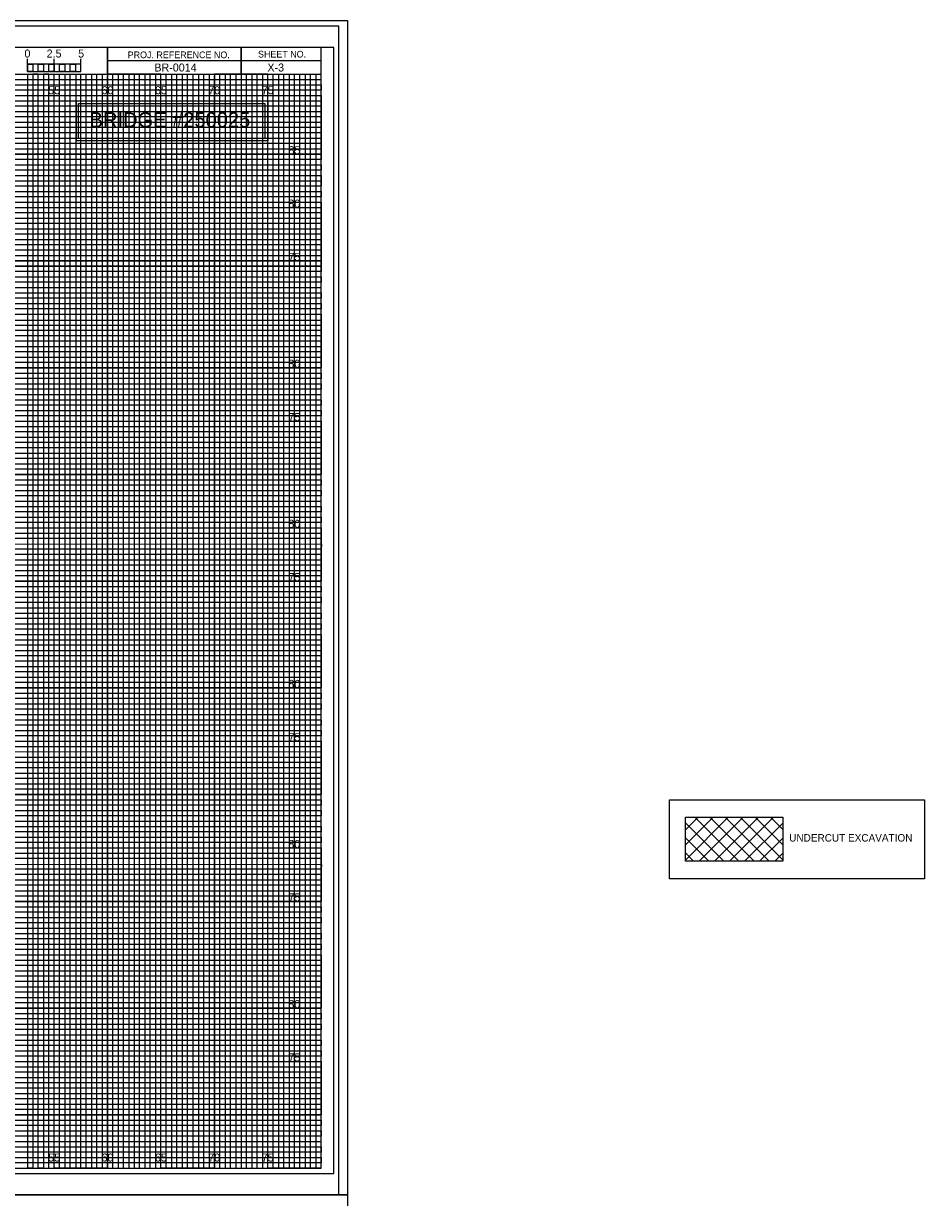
# Model space of a CAD drawing. Extents: x -8 to 533, y -20 to 768.
# Drawn here: x 132.1 to 216.5, y 217.2 to 327.2 of the extents above; entities that cross this region are included whole.
import ezdxf

# ---------------------------------------------------------------- set-up
doc = ezdxf.new("R2010")
doc.units = 0
for name, color, linetype in [('Old_Level_1', 7, 'Continuous'), ('Old_Level_34', 7, 'Continuous'), ('Prop Grid Mask', 7, 'Continuous'), ('Prop XS Bar Scale Labels', 7, 'Continuous'), ('Prop XS Elevation Labels', 7, 'Continuous'), ('Prop XS Offset Labels', 7, 'Continuous'), ('Prop XS Project Number', 7, 'Continuous'), ('Prop XS Sheet Number', 7, 'Continuous'), ('Prop XS Side Slope Text', 7, 'Continuous'), ('Prop XS Undercut Exc', 7, 'Continuous'), ('Sheet Cross Section CELL', 7, 'Continuous'), ('Sheet Cross Section Grid Major CELL', 7, 'Continuous'), ('Sheet Cross Section Grid Middle CELL', 7, 'Continuous'), ('Sheet Cross Section Grid Minor 1 CELL', 7, 'Continuous'), ('Sheet Cross Section Grid Minor 2 CELL', 7, 'Continuous'), ('Sheet Cross Section Scale CELL', 7, 'Continuous'), ('Sheet Cutting Line CELL', 7, 'Continuous'), ('Sheet DOT Grid CELL', 7, 'Continuous'), ('Sheet Plot Border Inside CELL', 7, 'Continuous'), ('Sheet Plot Border Outside CELL', 7, 'Continuous'), ('WEI Plot Border', 7, 'Continuous')]:
    doc.layers.add(name, color=color, linetype=linetype)

msp = doc.modelspace()

# ---------------------------------------------------------------- linework, layer by layer
at = {"layer": 'Old_Level_34'}
msp.add_lwpolyline([(137.26, 319.75), (154.74, 319.75), (154.74, 316.46), (137.26, 316.46)], close=True, dxfattribs=at)
at = {"layer": 'Prop Grid Mask'}
for points in [[(137.08, 320), (155, 320), (155, 316.24), (137.08, 316.24)], [(192.64, 254.5), (216.53, 254.5), (216.53, 247.11), (192.64, 247.11)]]:
    msp.add_lwpolyline(points, close=True, dxfattribs=at)
at = {"layer": 'Prop XS Undercut Exc'}
for p, q in [((194.13, 248.87), (198.14, 252.88)), ((194.13, 250.29), (196.73, 252.88)), ((194.13, 251.7), (195.31, 252.88)), ((194.13, 252.36), (197.73, 248.76)), ((195.01, 252.88), (199.14, 248.76)), ((195.43, 248.76), (199.55, 252.88)), ((196.43, 252.88), (200.56, 248.76)), ((196.84, 248.76), (200.97, 252.88)), ((197.84, 252.88), (201.97, 248.76)), ((198.25, 248.76), (202.38, 252.88)), ((199.26, 252.88), (203.25, 248.89)), ((199.67, 248.76), (203.25, 252.34)), ((200.67, 252.88), (203.25, 250.31)), ((202.09, 252.88), (203.25, 251.72)), ((194.13, 250.94), (196.31, 248.76)), ((201.08, 248.76), (203.25, 250.92)), ((194.13, 249.53), (194.9, 248.76)), ((202.5, 248.76), (203.25, 249.51))]:
    msp.add_line(p, q, dxfattribs=at)
msp.add_lwpolyline([(194.13, 252.88), (203.25, 252.88), (203.25, 248.76), (194.13, 248.76)], close=True, dxfattribs=at)
at = {"layer": 'Sheet Cross Section CELL'}
for p, q in [((152.5, 325), (152.5, 322.5)), ((152.5, 322.5), (152.5, 325)), ((160, 323.75), (140, 323.75)), ((140, 323.75), (140, 322.5)), ((140, 322.5), (160, 322.5))]:
    msp.add_line(p, q, dxfattribs=at)
for points in [[(160, 325), (0, 325), (0, 220), (160, 220)], [(140, 325), (130, 325), (130, 322.51), (140, 322.51)], [(160, 325), (140, 325), (140, 322.5), (160, 322.5)]]:
    msp.add_lwpolyline(points, close=True, dxfattribs=at)
at = {"layer": 'Sheet Cross Section Grid Major CELL'}
for p, q in [((135, 220), (135, 322.5)), ((145, 322.5), (140, 322.5)), ((140, 322.5), (140, 220)), ((145, 220), (145, 322.5)), ((155, 322.5), (150, 322.5)), ((150, 322.5), (150, 220)), ((155, 220), (155, 322.5)), ((140, 220), (135, 220)), ((150, 220), (145, 220)), ((160, 220), (155, 220)), ((160, 220), (160, 220))]:
    msp.add_line(p, q, dxfattribs=at)
for points in [[(0, 320), (160, 320), (160, 315), (0, 315)], [(0, 310), (160, 310), (160, 305), (0, 305)], [(0, 300), (160, 300), (160, 295), (0, 295)], [(0, 290), (160, 290), (160, 285), (0, 285)], [(0, 280), (160, 280), (160, 275), (0, 275)], [(0, 270), (160, 270), (160, 265), (0, 265)], [(0, 260), (160, 260), (160, 255), (0, 255)], [(0, 250), (160, 250), (160, 245), (0, 245)], [(0, 240), (160, 240), (160, 235), (0, 235)], [(0, 230), (160, 230), (160, 225), (0, 225)]]:
    msp.add_lwpolyline(points, dxfattribs=at)
at = {"layer": 'Sheet Cross Section Grid Middle CELL'}
for points in [[(0, 322.5), (137.5, 322.5)], [(130, 322.5), (132.5, 322.5), (132.5, 220), (137.5, 220), (137.5, 322.5), (142.5, 322.5), (142.5, 220), (147.5, 220), (147.5, 322.5), (152.5, 322.5), (152.5, 220), (157.5, 220), (157.5, 322.5)], [(0, 312.5), (160, 312.5), (160, 317.5), (0, 317.5)], [(0, 302.5), (160, 302.5), (160, 307.5), (0, 307.5)], [(0, 292.5), (160, 292.5), (160, 297.5), (0, 297.5)], [(0, 282.5), (160, 282.5), (160, 287.5), (0, 287.5)], [(0, 272.5), (160, 272.5), (160, 277.5), (0, 277.5)], [(0, 262.5), (160, 262.5), (160, 267.5), (0, 267.5)], [(0, 252.5), (160, 252.5), (160, 257.5), (0, 257.5)], [(0, 242.5), (160, 242.5), (160, 247.5), (0, 247.5)], [(0, 232.5), (160, 232.5), (160, 237.5), (0, 237.5)], [(0, 222.5), (160, 222.5), (160, 227.5), (0, 227.5)]]:
    msp.add_lwpolyline(points, dxfattribs=at)
at = {"layer": 'Sheet Cross Section Grid Minor 1 CELL'}
msp.add_line((0, 322), (160, 322), dxfattribs=at)
for points in [[(0, 321.5), (135, 321.5), (160, 321.5), (160, 321), (0, 321)], [(0, 320.5), (160, 320.5), (160, 319.5), (0, 319.5)], [(0, 319), (160, 319), (160, 318.5), (0, 318.49)], [(0, 318), (160, 318), (160, 317), (0, 317)], [(0, 316.5), (160, 316.5), (160, 316), (0, 316)], [(0, 315.5), (160, 315.5), (160, 314.5), (0, 314.5)], [(0, 314), (160, 314), (160, 313.5), (0, 313.5)], [(0, 313), (160, 313), (160, 312), (0, 312)], [(0, 311.5), (160, 311.5), (160, 311), (0, 311)], [(0, 310.5), (160, 310.5), (160, 309.5), (0, 309.5)], [(0, 309), (160, 309), (160, 308.5), (0, 308.5)], [(0, 308), (160, 308), (160, 306.98), (160, 306.5), (160, 306), (0, 306)], [(0, 307), (160, 307), (160, 306.5), (0, 306.5)], [(0, 305.5), (160, 305.5), (160, 304.5), (0, 304.51)], [(0, 304.51), (160, 304.5), (160, 304), (0, 304)], [(0, 303.5), (160, 303.5), (160, 303), (0, 303)], [(0, 302), (160, 302), (160, 301.5), (0, 301.5)], [(0, 301), (160, 301), (160, 300.5), (0, 300.5)], [(-0.04, 299.44), (160, 299.44), (160, 298.94), (-0.04, 298.94)], [(0, 298.5), (160, 298.5), (160, 298), (0, 298)], [(0, 297), (160, 297), (160, 296.5), (0, 296.5)], [(0, 296), (160, 296), (160, 295.5), (0, 295.5)], [(0, 294.5), (160, 294.5), (160, 294), (0, 294)], [(0, 293.5), (160, 293.5), (160, 293), (0, 293)], [(0, 292), (160, 292), (160, 291.5), (0, 291.5)], [(0, 291), (160, 291), (160, 290.5), (0, 290.5)], [(0, 289.5), (160, 289.5), (160, 288.99), (0, 289)], [(0, 288.5), (160, 288.5), (160, 288), (0, 288)], [(0, 287), (160, 287), (160, 286.5), (0, 286.5)], [(0, 286), (160, 286), (160, 285.5), (0, 285.5)], [(0, 284.5), (160, 284.5), (160, 284), (0, 284)], [(0, 283.5), (160, 283.5), (160, 283), (0, 283)], [(0, 282), (160, 282), (160, 281.5), (0, 281.5)], [(0, 281), (160, 281), (160, 280.5), (0, 280.5)], [(0, 279.5), (160, 279.5), (160, 279), (0, 279)], [(0, 278.5), (160.03, 278.45), (160, 278), (0, 278)], [(0, 277), (160, 277), (160, 276.5), (0, 276.5)], [(0, 276), (160, 276), (160, 275.5), (0, 275.5)], [(0, 274.5), (160, 274.5), (160, 274), (0, 274)], [(0, 273.5), (160, 273.5), (160, 273), (0, 273)], [(0, 272), (160, 272), (160, 271.5), (0, 271.5)], [(0, 271), (160, 271), (160, 270.5), (0, 270.5)], [(0, 269.5), (160, 269.5), (160, 269), (0, 269)], [(0, 268.5), (160, 268.5), (160, 268), (0, 268)], [(0, 267), (160, 267), (160, 266.5), (0, 266.5)], [(0, 266), (160, 266), (160, 265.5), (0, 265.5)], [(0, 264.5), (160, 264.5), (160, 264), (0, 264)], [(0, 263.5), (160, 263.5), (160, 263), (0, 263)], [(0, 262), (160, 262), (160, 261.5), (0, 261.5)], [(0, 261), (160, 261), (160, 260.5), (0, 260.5)], [(0, 259.5), (160, 259.5), (160, 258.99), (0, 259)], [(0, 258.5), (160, 258.5), (160, 258), (0, 258)], [(0, 257), (160, 257), (160, 256.5), (0, 256.5)], [(0, 256), (160, 256), (160, 255.5), (0, 255.5)], [(0, 254.5), (160, 254.5), (160, 254), (0, 254)], [(0, 253.5), (160, 253.5), (160, 253), (0, 253)], [(0, 252), (160, 252), (160, 251.5), (0, 251.5)], [(0, 251), (160, 251), (160, 250.5), (0, 250.5)], [(0, 249.5), (160, 249.5), (160, 249), (0, 249)], [(0, 248.5), (160.03, 248.46), (160, 248), (0, 248)], [(0, 247), (160, 247), (160, 246.5), (0, 246.5)], [(0, 246), (160, 246), (160, 245.5), (0, 245.5)], [(0, 244.5), (160, 244.5), (160, 244), (0, 244)], [(0, 243.5), (160, 243.5), (160, 243), (0, 243)], [(0, 242), (160, 242), (160, 241.5), (0, 241.5)], [(0, 241), (160, 241), (160, 240.5), (0, 240.5)], [(0, 239.5), (160, 239.5), (160, 239), (0, 239)], [(0, 238.5), (160, 238.5), (160, 238), (0, 238)], [(0, 237), (160, 237), (160, 236.5), (0, 236.5)], [(0, 236), (160, 236), (160, 235.5), (0, 235.5)], [(0, 234.5), (160, 234.5), (160, 234), (0, 234)], [(0, 233.5), (160, 233.5), (160, 233), (0, 233)], [(0, 232), (160, 232), (160, 231.5), (0, 231.5)], [(0, 231), (160, 231), (160, 230.5), (0, 230.5)], [(0, 229.5), (160, 229.5), (160, 229), (0, 229)], [(0, 228.5), (160, 228.5), (160, 228), (0, 228)], [(0, 227), (160, 227), (160, 226.5), (0, 226.5)], [(0, 226), (160, 226), (160, 225.5), (0, 225.5)], [(0, 224.5), (160, 224.5), (160, 224), (0, 224)], [(0, 223.5), (160, 223.5), (160, 223), (0, 223)], [(0, 222), (160, 222), (160, 221.5), (0, 221.5)], [(0, 221), (160, 221), (160, 220.5), (0, 220.5)]]:
    msp.add_lwpolyline(points, dxfattribs=at)
at = {"layer": 'Sheet Cross Section Grid Minor 2 CELL'}
for p, q in [((133.5, 322.5), (133, 322.5)), ((133, 322.5), (133, 220)), ((133.5, 220), (133.5, 322.5)), ((134.5, 322.5), (134, 322.5)), ((134, 322.5), (134, 220)), ((134.5, 220), (134.5, 322.5)), ((133, 220), (132.5, 220)), ((134, 220), (133.5, 220))]:
    msp.add_line(p, q, dxfattribs=at)
for points in [[(135, 220), (135.49, 220), (135.49, 322.5), (136, 322.5), (136, 220)], [(136, 220), (136.5, 220), (136.5, 322.5), (137.03, 322.5), (137.03, 220)], [(137.5, 220), (138, 220), (138, 322.5), (138.5, 322.5), (138.5, 220)], [(138.5, 220), (139, 220), (139, 322.5), (139.5, 322.5), (139.5, 220)], [(140, 220), (140.5, 220), (140.5, 322.5), (141, 322.5), (141, 220)], [(141, 220), (141.5, 220), (141.5, 322.5), (142, 322.5), (142, 220)], [(142.5, 220), (143, 220), (143, 322.5), (143.5, 322.5), (143.5, 220)], [(143.5, 220), (144, 220), (144, 322.5), (144.5, 322.5), (144.5, 220)], [(145, 220), (145.5, 220), (145.5, 322.5), (146, 322.5), (146, 220)], [(146, 220), (146.5, 220), (146.5, 322.5), (147, 322.5), (147, 220)], [(147.5, 220), (148, 220), (148, 322.5), (148.5, 322.5), (148.5, 220)], [(148.5, 220), (149, 220), (149, 322.5), (149.5, 322.5), (149.5, 220)], [(150, 220), (150.5, 220), (150.5, 322.5), (151, 322.5), (151, 220)], [(151, 220), (151.5, 220), (151.5, 322.5), (152, 322.5), (152, 220)], [(152.5, 220), (153, 220), (153, 322.5), (153.5, 322.5), (153.5, 220)], [(153.5, 220), (154, 220), (154, 322.5), (154.5, 322.5), (154.5, 220)], [(155, 220), (155.5, 220), (155.5, 322.5), (156, 322.5), (156, 220)], [(156, 220), (156.5, 220), (156.5, 322.5), (157, 322.5), (157, 220)], [(157.5, 220), (158, 220), (158, 322.5), (158.5, 322.5), (158.5, 220)], [(158.5, 220), (159, 220), (159, 322.5), (159.5, 322.5), (159.5, 220)]]:
    msp.add_lwpolyline(points, dxfattribs=at)
at = {"layer": 'Sheet Cross Section Scale CELL'}
for p, q in [((132.5, 322.75), (132.5, 323.95)), ((132.5, 323.45), (132.5, 323.95)), ((135, 322.75), (135, 323.95)), ((137.5, 322.75), (137.5, 323.95)), ((137.5, 323.45), (137.5, 323.95))]:
    msp.add_line(p, q, dxfattribs=at)
for points in [[(137.5, 323.45), (132.5, 323.45), (132.5, 322.75), (137.5, 322.75)], [(132.5, 323.45), (133, 323.45), (133, 322.75), (132.5, 322.75)], [(133.5, 323.45), (134, 323.45), (134, 322.75), (133.5, 322.75)], [(134.5, 323.45), (135, 323.45), (135, 322.75), (134.5, 322.75)], [(135.5, 323.45), (136, 323.45), (136, 322.75), (135.5, 322.75)], [(136.5, 323.45), (137, 323.45), (137, 322.75), (136.5, 322.75)]]:
    msp.add_lwpolyline(points, close=True, dxfattribs=at)
at = {"layer": 'Sheet Cutting Line CELL'}
for p, q in [((161.65, 327), (-6.7, 327)), ((-6.7, 217.5), (161.65, 217.5))]:
    msp.add_line(p, q, dxfattribs=at)
at = {"layer": 'Sheet DOT Grid CELL'}
for p, q in [((135, 220), (135, 322.34)), ((140, 220), (140, 322.34)), ((145, 220), (145, 322.34)), ((150, 220), (150, 322.34)), ((155, 220), (155, 322.34)), ((0, 320), (160, 320)), ((0, 315), (160, 315)), ((0, 310), (160, 310)), ((0, 305), (160, 305)), ((0, 300), (160, 300)), ((0, 295), (160, 295)), ((0, 290), (160, 290)), ((0, 285), (160, 285)), ((0, 280), (160, 280)), ((0, 275), (160, 275)), ((0, 270), (160, 270)), ((0, 265), (160, 265)), ((0, 260), (160, 260)), ((0, 255), (160, 255)), ((0, 250), (160, 250)), ((0, 245), (160, 245)), ((0, 240), (160, 240)), ((0, 235), (160, 235)), ((0, 230), (160, 230)), ((0, 225), (160, 225))]:
    msp.add_line(p, q, dxfattribs=at)
at = {"layer": 'Sheet Plot Border Inside CELL'}
msp.add_lwpolyline([(-5.4, 219.5), (161.2, 219.5), (161.2, 325), (-5.4, 325)], close=True, dxfattribs=at)
at = {"layer": 'Sheet Plot Border Outside CELL'}
msp.add_lwpolyline([(-6.7, 217.5), (161.65, 217.5), (161.65, 327), (-6.7, 327)], close=True, dxfattribs=at)
at = {"layer": 'WEI Plot Border'}
for points in [[(-7.5, 217.5), (162.5, 217.5), (162.5, 327.5), (-7.5, 327.5)], [(-7.5, 107.5), (162.5, 107.5), (162.5, 217.5), (-7.5, 217.5)]]:
    msp.add_lwpolyline(points, close=True, dxfattribs=at)

# ---------------------------------------------------------------- texts
at = {"layer": 'Old_Level_1'}
msp.add_text('BRIDGE #250025', height=1.4062, rotation=360, dxfattribs=at).set_placement((138.31, 317.52))
at = {"layer": 'Prop XS Bar Scale Labels'}
for s, p in [('2.5', (134.29, 324.06)), ('5', (137.24, 324.06))]:
    msp.add_text(s, height=0.75, dxfattribs=at).set_placement(p)
at = {"layer": 'Prop XS Elevation Labels'}
for s, p in [('85', (156.94, 315)), ('80', (156.93, 310)), ('75', (156.94, 305)), ('80', (156.93, 295)), ('75', (156.94, 290)), ('80', (156.93, 280)), ('75', (156.94, 275)), ('80', (156.93, 265)), ('75', (156.94, 260)), ('80', (156.93, 250)), ('75', (156.94, 245)), ('80', (156.93, 235)), ('75', (156.94, 230))]:
    msp.add_text(s, height=0.75, dxfattribs=at).set_placement(p)
at = {"layer": 'Prop XS Offset Labels'}
for s, p in [('55', (134.44, 320.62)), ('60', (139.43, 320.62)), ('65', (144.44, 320.62)), ('70', (149.43, 320.62)), ('75', (154.44, 320.62)), ('55', (134.44, 220.62)), ('60', (139.43, 220.62)), ('65', (144.44, 220.62)), ('70', (149.43, 220.62)), ('75', (154.44, 220.62))]:
    msp.add_text(s, height=0.75, dxfattribs=at).set_placement(p)
at = {"layer": 'Prop XS Project Number'}
msp.add_text('BR-0014', height=0.75, dxfattribs=at).set_placement((144.38, 322.75))
at = {"layer": 'Prop XS Sheet Number'}
msp.add_text('X-3', height=0.75, dxfattribs=at).set_placement((154.97, 322.75))
at = {"layer": 'Prop XS Side Slope Text'}
msp.add_text('UNDERCUT EXCAVATION', height=0.7, dxfattribs=at).set_placement((203.85, 250.6))
at = {"layer": 'Sheet Cross Section CELL'}
for s, p in [('PROJ. REFERENCE NO.', (141.88, 324)), ('SHEET NO.', (154.09, 324.06))]:
    msp.add_text(s, height=0.625, dxfattribs=at).set_placement(p)
at = {"layer": 'Sheet Cross Section Scale CELL'}
msp.add_text('0', height=0.75, dxfattribs=at).set_placement((132.21, 324.06))

doc.saveas('drawing.dxf')
